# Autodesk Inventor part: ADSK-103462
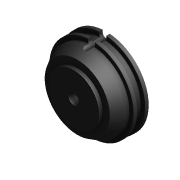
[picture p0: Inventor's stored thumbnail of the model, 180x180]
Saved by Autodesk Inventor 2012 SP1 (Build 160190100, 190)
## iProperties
Shininess: 0.0
Created: 2000-11
Part Number: ADSK-103462
Document SubType Name: Modeling
Designer: gao
Stock Number: ADSK-103462
Density: 1 g/cm^3
Material: Default
Density: 0.0
Volumn: 0.0
Area: 0.0
PropertySet Name: Model Information
Control State: 0
Master: False
Checked Out: False
Author: gao
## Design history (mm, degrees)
node "Extrusion1" dims "d1" = 9.525, "d2" = 0
  sketch "Sketch1"
    geometry: C1 r 114.3 at (0, 0)
    constraints: 1 centre point
    dimensions: "d0" = 228.6 diameter of C1
node "Extrusion2" dims "d4" = 20.828, "d5" = 0
  sketch "Sketch2"
    geometry: C1 r 114.3 at (0, 0) reference; C2 r 102.362 at (0, 0)
    constraints: 1 centre point, 1 coincident
    dimensions: "d3" = 204.724 diameter of C2
node "Extrusion3" dims "d6" = 9.525, "d7" = 0
  sketch "Sketch3"
    geometry: C1 r 102.362 at (0, 0) reference; C2 r 113.373 at (0, 0)
    constraints: 1 centre point, 1 coincident
node "Extrusion4" dims "d9" = 38.0365, "d10" = 0
  sketch "Sketch4"
    geometry: C1 r 113.373 at (0, 0) reference; C2 r 102.362 at (0, 0)
    constraints: 1 centre point, 1 coincident
    dimensions: "d8" = 204.724 diameter of C2
node "Extrusion5" dims "d11" = 9.525, "d12" = 0
  sketch "Sketch5"
    geometry: C1 r 102.362 at (0, 0) reference; C2 r 67.991 at (0, 0)
    constraints: 1 centre point, 1 coincident
node "Hole1" dims "d13" = 28, "d14" = 9.525, "d15" = 6.35, "d16" = 60 deg, "d17" = 19.05, "d18" = 118 deg
  sketch "Sketch6"
    geometry: C1 r 67.991 at (0, 0) reference; 1 further point
    constraints: 1 coincident
node "Chamfer1" dims "d19" = 25.4, "d20" = 30 deg, "d25" = 25.4
node "Extrusion6" dims "d23" = 9.525, "d24" = 0
  sketch "Sketch7"
    geometry: L1 (9.489, 107.95)-(9.489, 113.905); L2 (-9.561, 107.95)-(-9.561, 113.899); A1 r 114.3 centre (0, 0) between (9.489, 113.905) and (-9.561, 113.899) reference; A2 r 9.525 centre (-0.036, 107.95) between (-9.561, 107.95) and (9.489, 107.95)
    constraints: 4 end point, 4 point on circle, 2 tangent, 1 centre point, 1 parallel, 1 vertical
    dimensions: "d21" = 19.05 diameter of A2; "d22" = 107.95 distance of A1.centre A2.centre
body "Solid1"
